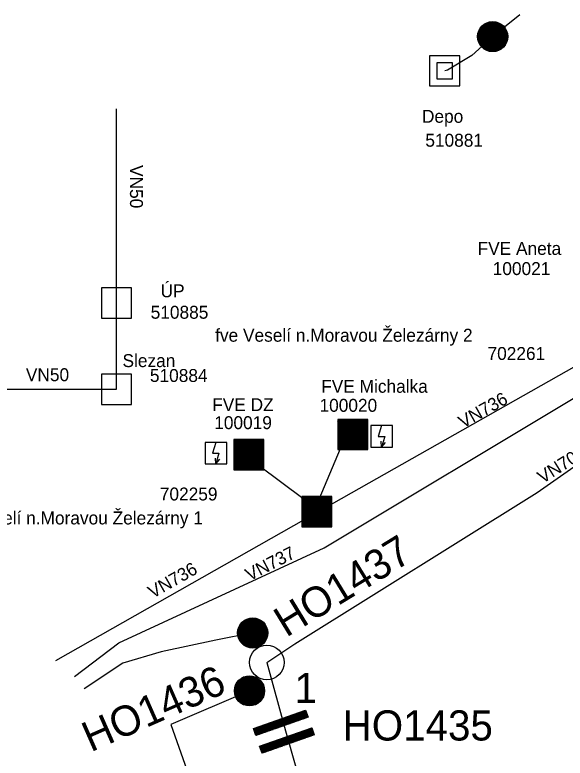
# Model space of a CAD drawing. Extents: x -546092 to -542700, y -1196659 to -1193917.
# Drawn here: x -545218 to -544579, y -1194828 to -1193966 of the extents above; entities that cross this region are included whole.
import ezdxf

# ---------------------------------------------------------------- set-up
doc = ezdxf.new("R2010")
doc.units = 0
for name, color, linetype in [('Default', 7, 'Continuous'), ('Vrstva 1', 7, 'Continuous'), ('Vrstva 18', 7, 'Continuous'), ('Vrstva 2', 7, 'Continuous'), ('Vrstva 20', 7, 'Continuous'), ('Vrstva 3', 7, 'Continuous'), ('Vrstva 4', 7, 'Continuous'), ('Vrstva 47', 7, 'Continuous'), ('Vrstva 5', 7, 'Continuous')]:
    doc.layers.add(name, color=color, linetype=linetype)

# ---------------------------------------------------------------- blocks, each defined once
blk = doc.blocks.new('PS700')
at = {"layer": 'Vrstva 47'}
for points in [[(12.48, 12.51), (-12.52, 12.51)], [(-12.52, 12.51), (-12.52, -12.49)], [(-0.02, 12.51), (-3.96, -0.19)], [(12.48, -12.49), (12.48, 12.51)], [(-3.96, -0.19), (3.52, -0.19)], [(-0.02, -12.49), (-0.71, -5.7)], [(3.52, -0.19), (-0.02, -12.49)], [(-0.02, -12.49), (4.31, -7.08)], [(-12.52, -12.49), (12.48, -12.49)]]:
    blk.add_lwpolyline(points, dxfattribs=at)
blk = doc.blocks.new('PS100')
at = {"layer": 'Default'}
for p, q in [((-17.47, -0.71), (0.71, 17.47)), ((-17.47, 0.7), (-0.7, 17.47)), ((-17.37, -2.02), (2.02, 17.37)), ((-17.34, 2.25), (-2.25, 17.34)), ((-17.18, -3.25), (3.25, 17.18)), ((-17.03, 3.97), (-3.97, 17.03)), ((-16.92, -4.41), (4.41, 16.92)), ((-16.6, -5.5), (5.5, 16.6)), ((-16.43, 5.99), (-5.99, 16.43)), ((-16.22, -6.53), (6.53, 16.22)), ((-15.79, -7.52), (7.52, 15.79)), ((-15.31, -8.45), (8.45, 15.31)), ((-15.22, 8.61), (-8.61, 15.22)), ((-14.78, -9.34), (9.34, 14.78)), ((-14.22, -10.18), (10.18, 14.22)), ((-13.6, -10.99), (10.99, 13.6)), ((-12.95, -11.75), (11.75, 12.95)), ((-12.26, -12.47), (12.47, 12.26)), ((-11.53, -13.15), (13.15, 11.53)), ((-10.75, -13.79), (13.79, 10.75)), ((-9.94, -14.39), (14.39, 9.94)), ((-9.08, -14.95), (14.95, 9.08)), ((-8.18, -15.46), (15.46, 8.18)), ((-7.23, -15.92), (15.92, 7.23)), ((-6.23, -16.34), (16.34, 6.23)), ((-5.18, -16.7), (16.7, 5.18)), ((-4.07, -17.01), (17.01, 4.07)), ((-2.89, -17.25), (17.25, 2.89)), ((-1.64, -17.41), (17.41, 1.64)), ((-0.3, -17.48), (17.48, 0.3)), ((1.15, -17.45), (17.45, -1.15)), ((2.74, -17.27), (17.27, -2.74)), ((4.54, -16.89), (16.89, -4.54)), ((6.68, -16.16), (16.16, -6.68)), ((9.71, -14.54), (14.54, -9.71))]:
    blk.add_line(p, q, dxfattribs=at)
blk.add_circle((0, 0), 17.49, dxfattribs=at)
blk = doc.blocks.new('PS140')
at = {"layer": 'Default'}
for p, q in [((-17.49, -0.01), (0.01, 17.49)), ((-17.43, -1.37), (1.37, 17.43)), ((-17.42, 1.47), (-1.47, 17.42)), ((-17.29, -2.63), (2.63, 17.29)), ((-17.21, 3.1), (-3.1, 17.21)), ((-17.06, -3.82), (3.82, 17.06)), ((-16.77, -4.95), (4.95, 16.77)), ((-16.77, 4.95), (-4.95, 16.77)), ((-16.42, -6.01), (6.01, 16.42)), ((-16.02, -7.02), (7.02, 16.02)), ((-15.93, 7.2), (-7.2, 15.93)), ((-15.56, -7.98), (7.98, 15.56)), ((-15.06, -8.89), (8.89, 15.06)), ((-14.51, -9.76), (9.76, 14.51)), ((-13.92, -10.58), (10.58, 13.92)), ((-13.75, 10.8), (-10.8, 13.75)), ((-13.29, -11.36), (11.36, 13.29)), ((-12.62, -12.11), (12.11, 12.62)), ((-11.91, -12.81), (12.81, 11.91)), ((-11.15, -13.47), (13.47, 11.15)), ((-10.36, -14.09), (14.09, 10.36)), ((-9.52, -14.67), (14.67, 9.52)), ((-8.64, -15.2), (15.2, 8.64)), ((-7.72, -15.69), (15.69, 7.72)), ((-6.74, -16.13), (16.13, 6.74)), ((-5.72, -16.52), (16.52, 5.72)), ((-4.64, -16.86), (16.86, 4.64)), ((-3.5, -17.13), (17.13, 3.5)), ((-2.29, -17.34), (17.34, 2.29)), ((-1, -17.46), (17.46, 1)), ((0.39, -17.48), (17.48, -0.39)), ((1.91, -17.38), (17.38, -1.91)), ((3.59, -17.11), (17.11, -3.59)), ((5.53, -16.59), (16.59, -5.53)), ((7.96, -15.57), (15.57, -7.96))]:
    blk.add_line(p, q, dxfattribs=at)
blk.add_circle((0, 0), 17.49, dxfattribs=at)
blk = doc.blocks.new('PS150')
at = {"layer": 'Default'}
for p, q in [((-15.07, 22.36), (-7.37, 30.07)), ((-15.07, 23.78), (-8.78, 30.07)), ((-15.07, 25.19), (-10.2, 30.07)), ((-15.07, 26.6), (-11.61, 30.07)), ((-15.07, 28.02), (-13.03, 30.07)), ((-15.07, 29.43), (-14.44, 30.07)), ((-15.07, 20.95), (-6.51, 29.51)), ((-15.07, 19.53), (-6.51, 28.1)), ((-15.07, 18.12), (-6.51, 26.69)), ((6.66, 22.61), (14.12, 30.07)), ((6.66, 24.02), (12.7, 30.06)), ((6.66, 25.43), (11.29, 30.06)), ((6.66, 26.85), (9.87, 30.06)), ((6.66, 28.26), (8.46, 30.06)), ((6.66, 29.68), (7.04, 30.06)), ((6.66, 21.19), (15.22, 29.76)), ((6.66, 19.78), (15.22, 28.34)), ((6.66, 18.36), (15.22, 26.93)), ((-15.07, 16.71), (-6.51, 25.27)), ((-15.07, 15.29), (-6.51, 23.86)), ((-15.07, 13.88), (-6.51, 22.44)), ((-15.07, 12.46), (-6.51, 21.03)), ((-15.07, 11.05), (-6.51, 19.61)), ((-15.07, 9.64), (-6.51, 18.2)), ((6.66, 16.95), (15.22, 25.51)), ((6.66, 15.54), (15.22, 24.1)), ((6.66, 14.12), (15.22, 22.69)), ((6.66, 12.71), (15.22, 21.27)), ((6.66, 11.29), (15.22, 19.86)), ((6.66, 9.88), (15.22, 18.44)), ((-15.07, 8.22), (-6.51, 16.79)), ((-15.07, 6.81), (-6.51, 15.37)), ((-15.07, 5.39), (-6.51, 13.96)), ((-15.07, 3.98), (-6.5, 12.54)), ((-15.07, 2.56), (-6.5, 11.13)), ((-15.07, 1.15), (-6.5, 9.72)), ((6.66, 8.46), (15.22, 17.03)), ((6.66, 7.05), (15.22, 15.62)), ((6.66, 5.64), (15.22, 14.2)), ((6.66, 4.22), (15.22, 12.79)), ((6.66, 2.81), (15.22, 11.37)), ((6.66, 1.39), (15.22, 9.96)), ((-15.07, -0.26), (-6.5, 8.3)), ((-15.07, -1.68), (-6.5, 6.89)), ((-15.07, -3.09), (-6.5, 5.47)), ((-15.07, -4.51), (-6.5, 4.06)), ((-15.07, -5.92), (-6.5, 2.65)), ((-15.07, -7.33), (-6.5, 1.23)), ((6.66, -0.02), (15.22, 8.55)), ((6.66, -1.43), (15.22, 7.13)), ((6.66, -2.85), (15.22, 5.72)), ((6.66, -4.26), (15.22, 4.3)), ((6.66, -5.68), (15.22, 2.89)), ((6.66, -7.09), (15.22, 1.47)), ((6.66, -8.5), (15.22, 0.06)), ((-15.07, -8.75), (-6.5, -0.18)), ((-15.07, -10.16), (-6.5, -1.6)), ((-15.07, -11.58), (-6.5, -3.01)), ((-15.07, -12.99), (-6.5, -4.43)), ((-15.07, -14.4), (-6.5, -5.84)), ((-15.07, -15.82), (-6.5, -7.25)), ((6.66, -9.92), (15.22, -1.35)), ((6.66, -11.33), (15.22, -2.77)), ((6.66, -12.75), (15.22, -4.18)), ((6.66, -14.16), (15.23, -5.6)), ((6.66, -15.58), (15.23, -7.01)), ((6.66, -16.99), (15.23, -8.42)), ((-15.07, -17.23), (-6.5, -8.67)), ((-15.07, -18.65), (-6.5, -10.08)), ((-15.07, -20.06), (-6.5, -11.5)), ((-15.07, -21.48), (-6.5, -12.91)), ((-15.07, -22.89), (-6.5, -14.32)), ((-15.07, -24.3), (-6.5, -15.74)), ((-15.07, -25.72), (-6.5, -17.15)), ((6.66, -18.4), (15.23, -9.84)), ((6.66, -19.82), (15.23, -11.25)), ((6.66, -21.23), (15.23, -12.67)), ((6.66, -22.65), (15.23, -14.08)), ((6.66, -24.06), (15.23, -15.49)), ((6.66, -25.47), (15.23, -16.91)), ((-15.07, -27.13), (-6.5, -18.57)), ((-15.07, -28.55), (-6.5, -19.98)), ((-15.07, -29.96), (-6.5, -21.39)), ((-15.07, -31.37), (-6.5, -22.81)), ((-15.07, -32.79), (-6.5, -24.22)), ((-15.02, -34.16), (-6.5, -25.64)), ((6.66, -26.89), (15.23, -18.32)), ((6.66, -28.3), (15.23, -19.74)), ((6.66, -29.72), (15.23, -21.15)), ((6.66, -31.13), (15.23, -22.57)), ((6.66, -32.54), (15.23, -23.98)), ((6.66, -33.96), (15.23, -25.39)), ((-13.61, -34.16), (-6.5, -27.05)), ((-12.2, -34.16), (-6.5, -28.47)), ((-10.78, -34.16), (-6.5, -29.88)), ((-9.37, -34.16), (-6.5, -31.29)), ((-7.95, -34.16), (-6.5, -32.71)), ((-6.54, -34.16), (-6.5, -34.12)), ((7.87, -34.16), (15.23, -26.81)), ((9.29, -34.16), (15.23, -28.22)), ((10.7, -34.16), (15.23, -29.64)), ((12.12, -34.16), (15.23, -31.05)), ((13.53, -34.16), (15.23, -32.46)), ((14.95, -34.16), (15.23, -33.88))]:
    blk.add_line(p, q, dxfattribs=at)
for points in [[(-6.51, 30.07), (-6.5, -34.16), (-15.07, -34.16), (-15.07, 30.07)], [(15.22, 30.07), (15.23, -34.16), (6.66, -34.16), (6.66, 30.06)]]:
    blk.add_lwpolyline(points, close=True, dxfattribs=at)
blk = doc.blocks.new('PS800')
at = {"layer": 'Vrstva 2'}
blk.add_circle((0, -0.01), 20, dxfattribs=at)
blk = doc.blocks.new('PS650')
at = {"layer": 'Vrstva 20'}
for points in [[(17.5, 17.5), (-17.5, 17.5)], [(-17.5, 17.5), (-17.5, -17.5)], [(17.5, -17.5), (17.5, 17.5)], [(-17.5, -17.5), (17.5, -17.5)]]:
    blk.add_lwpolyline(points, dxfattribs=at)
blk = doc.blocks.new('PS630')
at = {"layer": 'Default'}
for p, q in [((-16.61, -14.95), (17.07, 18.74)), ((-16.61, -13.53), (15.66, 18.74)), ((-16.61, -12.12), (14.24, 18.74)), ((-16.61, -10.71), (12.83, 18.74)), ((-16.61, -9.29), (11.41, 18.74)), ((-16.61, -7.88), (10, 18.74)), ((-16.61, -6.46), (8.59, 18.74)), ((-16.61, -5.05), (7.17, 18.74)), ((-16.61, -3.63), (5.76, 18.74)), ((-16.61, -2.22), (4.34, 18.74)), ((-16.61, -0.81), (2.93, 18.74)), ((-16.61, 0.61), (1.51, 18.74)), ((-16.61, 2.02), (0.1, 18.74)), ((-16.61, 3.44), (-1.31, 18.74)), ((-16.61, 4.85), (-2.73, 18.74)), ((-16.61, 6.27), (-4.14, 18.74)), ((-16.61, 7.68), (-5.56, 18.74)), ((-16.61, 9.09), (-6.97, 18.74)), ((-16.61, 10.51), (-8.38, 18.74)), ((-16.61, 11.92), (-9.8, 18.74)), ((-16.61, 13.34), (-11.21, 18.74)), ((-16.61, 14.75), (-12.63, 18.74)), ((-16.61, 16.16), (-14.04, 18.74)), ((-16.61, 17.58), (-15.46, 18.74)), ((-16.51, -16.26), (18.39, 18.64)), ((-15.1, -16.26), (18.39, 17.22)), ((-13.69, -16.26), (18.39, 15.81)), ((-12.27, -16.26), (18.39, 14.39)), ((-10.86, -16.26), (18.39, 12.98)), ((-9.44, -16.26), (18.39, 11.57)), ((-8.03, -16.26), (18.39, 10.15)), ((-6.62, -16.26), (18.39, 8.74)), ((-5.2, -16.26), (18.39, 7.32)), ((-3.79, -16.26), (18.39, 5.91)), ((-2.37, -16.26), (18.39, 4.5)), ((-0.96, -16.26), (18.39, 3.08)), ((0.46, -16.26), (18.39, 1.67)), ((1.87, -16.26), (18.39, 0.25)), ((3.28, -16.26), (18.39, -1.16)), ((4.7, -16.26), (18.39, -2.58)), ((6.11, -16.26), (18.39, -3.99)), ((7.53, -16.26), (18.39, -5.4)), ((8.94, -16.26), (18.39, -6.82)), ((10.36, -16.26), (18.39, -8.23)), ((11.77, -16.26), (18.39, -9.65)), ((13.18, -16.26), (18.39, -11.06)), ((14.6, -16.26), (18.39, -12.48)), ((16.01, -16.26), (18.39, -13.89)), ((17.43, -16.26), (18.39, -15.3))]:
    blk.add_line(p, q, dxfattribs=at)
for points in [[(-16.61, 18.74), (-16.61, -16.26)], [(18.39, 18.74), (-16.61, 18.74)], [(-16.61, 18.74), (-16.61, -16.26)], [(18.39, -16.26), (18.39, 18.74)], [(-16.61, -16.26), (18.39, -16.26)]]:
    blk.add_lwpolyline(points, dxfattribs=at)
blk = doc.blocks.new('PS651')
at = {"layer": 'Vrstva 20'}
for points in [[(17.5, 17.5), (-17.5, 17.5)], [(-17.5, 17.5), (-17.5, -17.5)], [(17.5, -17.5), (17.5, 17.5)], [(-17.5, -17.5), (17.5, -17.5)]]:
    blk.add_lwpolyline(points, dxfattribs=at)
blk = doc.blocks.new('PS641')
at = {"layer": 'Vrstva 18'}
for points in [[(17.5, 17.53), (-17.5, 17.53)], [(-17.5, 17.53), (-17.5, -17.47)], [(17.5, -17.47), (17.5, 17.53)], [(9.23, 9.26), (-9.23, 9.26)], [(-9.23, 9.26), (-9.23, -9.2)], [(9.23, -9.2), (9.23, 9.26)], [(-9.23, -9.2), (9.23, -9.2)], [(-17.5, -17.47), (17.5, -17.47)]]:
    blk.add_lwpolyline(points, dxfattribs=at)
blk = doc.blocks.new('PS631')
at = {"layer": 'Default'}
for p, q in [((-16.61, -14.95), (17.07, 18.74)), ((-16.61, -13.53), (15.66, 18.74)), ((-16.61, -12.12), (14.24, 18.74)), ((-16.61, -10.71), (12.83, 18.74)), ((-16.61, -9.29), (11.41, 18.74)), ((-16.61, -7.88), (10, 18.74)), ((-16.61, -6.46), (8.59, 18.74)), ((-16.61, -5.05), (7.17, 18.74)), ((-16.61, -3.63), (5.76, 18.74)), ((-16.61, -2.22), (4.34, 18.74)), ((-16.61, -0.81), (2.93, 18.74)), ((-16.61, 0.61), (1.51, 18.74)), ((-16.61, 2.02), (0.1, 18.74)), ((-16.61, 3.44), (-1.31, 18.74)), ((-16.61, 4.85), (-2.73, 18.74)), ((-16.61, 6.27), (-4.14, 18.74)), ((-16.61, 7.68), (-5.56, 18.74)), ((-16.61, 9.09), (-6.97, 18.74)), ((-16.61, 10.51), (-8.38, 18.74)), ((-16.61, 11.92), (-9.8, 18.74)), ((-16.61, 13.34), (-11.21, 18.74)), ((-16.61, 14.75), (-12.63, 18.74)), ((-16.61, 16.16), (-14.04, 18.74)), ((-16.61, 17.58), (-15.46, 18.74)), ((-16.51, -16.26), (18.39, 18.64)), ((-15.1, -16.26), (18.39, 17.22)), ((-13.69, -16.26), (18.39, 15.81)), ((-12.27, -16.26), (18.39, 14.39)), ((-10.86, -16.26), (18.39, 12.98)), ((-9.44, -16.26), (18.39, 11.57)), ((-8.03, -16.26), (18.39, 10.15)), ((-6.62, -16.26), (18.39, 8.74)), ((-5.2, -16.26), (18.39, 7.32)), ((-3.79, -16.26), (18.39, 5.91)), ((-2.37, -16.26), (18.39, 4.5)), ((-0.96, -16.26), (18.39, 3.08)), ((0.46, -16.26), (18.39, 1.67)), ((1.87, -16.26), (18.39, 0.25)), ((3.28, -16.26), (18.39, -1.16)), ((4.7, -16.26), (18.39, -2.58)), ((6.11, -16.26), (18.39, -3.99)), ((7.53, -16.26), (18.39, -5.4)), ((8.94, -16.26), (18.39, -6.82)), ((10.36, -16.26), (18.39, -8.23)), ((11.77, -16.26), (18.39, -9.65)), ((13.18, -16.26), (18.39, -11.06)), ((14.6, -16.26), (18.39, -12.48)), ((16.01, -16.26), (18.39, -13.89)), ((17.43, -16.26), (18.39, -15.3))]:
    blk.add_line(p, q, dxfattribs=at)
for points in [[(-16.61, 18.74), (-16.61, -16.26)], [(18.39, 18.74), (-16.61, 18.74)], [(-16.61, 18.74), (-16.61, -16.26)], [(18.39, -16.26), (18.39, 18.74)], [(-16.61, -16.26), (18.39, -16.26)]]:
    blk.add_lwpolyline(points, dxfattribs=at)

msp = doc.modelspace()

# ---------------------------------------------------------------- linework, layer by layer
at = {"layer": 'Vrstva 1'}
for points in [[(-544631.79, -1193965.65), (-544663.41, -1193990.83)], [(-544663.41, -1193990.83), (-544663.41, -1193990.83), (-544687.52, -1194012.96), (-544715.85, -1194029.76), (-544719.08, -1194030.61)], [(-545100, -1194300), (-545100, -1194074.69)], [(-544925.5, -1194716.9), (-544893.06, -1194695.43), (-544611.95, -1194519.78), (-544508.51, -1194447.58), (-544419.53, -1194386.55), (-544355.13, -1194265.22), (-544366.07, -1194232.09)], [(-545100, -1194350), (-545100, -1194300)], [(-545100, -1194400), (-545100, -1194350)], [(-545148.86, -1194733.03), (-545097.22, -1194694.01), (-544858.8, -1194583.9), (-544566.1, -1194408.5), (-544557.1, -1194367.2)], [(-544868.4, -1194543.3), (-544557.1, -1194367.2)], [(-545250, -1194400), (-545100, -1194400)], [(-544864.6, -1194527.54), (-544839.94, -1194468.68)], [(-544883.56, -1194526.74), (-544934.15, -1194489.18)], [(-545170.41, -1194714.45), (-544868.4, -1194543.3)], [(-544941.89, -1194682.68), (-544984.9, -1194690.9), (-545048.18, -1194704.42), (-545092.76, -1194717.8), (-545137.34, -1194747.53)], [(-544925.5, -1194716.9), (-544903.86, -1194796.41)], [(-544945.65, -1194749.85), (-545036.86, -1194788.98), (-544971.48, -1194974.06), (-544918.9, -1195027.43)], [(-544903.86, -1194796.41), (-544879.02, -1194883.37)]]:
    msp.add_lwpolyline(points, dxfattribs=at)

# ---------------------------------------------------------------- block references
at = {"layer": 'Vrstva 2'}
for name, p, rotation in [('PS140', (-544663.41, -1193990.83), 36.557361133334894), ('PS100', (-544941.89, -1194682.68), 34.61069450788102), ('PS100', (-544945.65, -1194749.85), 43.41062498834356), ('PS150', (-544903.86, -1194796.41), -70.69475973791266)]:
    msp.add_blockref(name, p, dxfattribs=dict(at, rotation=rotation))
at = {"layer": 'Vrstva 3'}
for name, p in [('PS641', (-544719.08, -1194030.61)), ('PS650', (-545100, -1194300)), ('PS651', (-545100, -1194400)), ('PS631', (-544826.62, -1194453.76)), ('PS631', (-544947.24, -1194477.08)), ('PS630', (-544868.4, -1194543.3))]:
    msp.add_blockref(name, p, dxfattribs=at)
at = {"layer": 'Vrstva 4'}
for p in [(-544792.24, -1194454.49), (-544984.57, -1194474.06)]:
    msp.add_blockref('PS700', p, dxfattribs=at)
at = {"layer": 'Vrstva 5', "rotation": -55.3893055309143}
msp.add_blockref('PS800', (-544925.5, -1194716.9), dxfattribs=at)

# ---------------------------------------------------------------- texts
at = {"layer": 'Vrstva 1'}
for s, rotation, p in [('VN50', 270, (-545084.36, -1194139.88)), ('VN736', 29.497, (-544697.82, -1194445.75)), ('VN704', 31.999, (-544605.47, -1194509.9)), ('VN737', 27.21, (-544945.54, -1194622.89)), ('VN736', 29.541, (-545058.02, -1194643.05))]:
    msp.add_text(s, height=15, rotation=rotation, dxfattribs=at).set_placement(p)
msp.add_text('VN50', height=15, dxfattribs=at).set_placement((-545205.17, -1194390.62))
at = {"layer": 'Vrstva 2'}
for s, rotation, p in [('HO1437', 31.464, (-544903.04, -1194688.34)), ('HO1436', 23.769, (-545129.93, -1194821.3))]:
    msp.add_text(s, height=35, rotation=rotation, dxfattribs=at).set_placement(p)
msp.add_text('HO1435', height=35, dxfattribs=at).set_placement((-544837.52, -1194807.46))
at = {"layer": 'Vrstva 3'}
for s, p in [('Depo', (-544745.49, -1194090.84)), ('510881', (-544741.57, -1194118.59)), ('FVE Aneta', (-544680.9, -1194244.11)), ('100021', (-544663.37, -1194267.49)), ('ÚP', (-545048.82, -1194293.3)), ('510885', (-545060.34, -1194318.16)), ('fve Veselí n.Moravou Železárny 2', (-544985.5, -1194344.82)), ('702261', (-544669.39, -1194365.98)), ('Slezan', (-545093.05, -1194374.27)), ('510884', (-545061.24, -1194391.51)), ('FVE Michalka', (-544862.4, -1194404.05)), ('FVE DZ', (-544988.94, -1194425.34)), ('100020', (-544864.38, -1194426.12)), ('100019', (-544986.58, -1194446.23)), ('702259', (-545049.72, -1194528.98)), ('fve Veselí n.Moravou Železárny 1', (-545298.51, -1194556.77))]:
    msp.add_text(s, height=15, dxfattribs=at).set_placement(p)
at = {"layer": 'Vrstva 5'}
msp.add_text('1', height=35, dxfattribs=at).set_placement((-544893.37, -1194764.02))

doc.saveas('drawing.dxf')
